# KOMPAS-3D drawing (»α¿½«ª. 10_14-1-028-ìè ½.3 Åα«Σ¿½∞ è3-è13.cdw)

Referenced files in C:\Program Files\ASCON\KOMPAS-3D V10\Sys\: SPDS.lcs, Graphic.lcs
Referenced files: профиль К3-К13.cdw
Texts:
  Текст на чертеже
  Размерные надписи
  Шероховатость
  Линия-выноска #1
  Линия-выноска #2
  Линия-выноска #3
  Отклонения формы и база
  Заголовок таблицы
  Ячейка таблицы
  Стрелка вида
  Обозначение изменения
  Фигурная скобка
  Номер узла
  Марка координационной оси
  VRCB
  Выносная надпись
  Обозначение узла
  Марка/позиционное обозначение с линией-выноской
  Марка/позиционное обозначение на линии
  Марка/позиционное обозначение без линии-выноски
  Normal
  TXT
  Courier New Cyr
  txt
  Body Text
  heading 1
  Знак Знак Знак Знак Знак Знак
  Verdana
  Лит-Масса-Масштаб
  Материал-Предприятие
  MS Sans Serif
  Simplex
  Txt
  Title Specification
  Body Specification ( left align )
  Body Specificaton ( centered )
  Без имени
  Additional DXF text style 0
  Обычный
  Термин
  Список определений
  Адрес
  Цитаты
  Форматированный
  Courier New
  Z-конец формы
  Z-начало формы
  ТекстШаг1
  Денис
  heading 2
  AGOpus
  footer
  Title
  ООббыыччнныыйй
  Definition Term
  Definition List
  Address
  Blockquote
  Preformatted
  z-Bottom of Form
  z-Top of Form
  header
  heading 8
  heading 3
  heading 6
  heading 7
  russ
  ТТееррммиинн
  ССппииссоокк ооппррееддееллеенниийй
  ААддрреесс
  ЦЦииттааттыы
  ФФооррммааттиирроовваанннныыйй
  Z-ккооннеецц ффооррммыы
  Z-ннааччааллоо ффооррммыы
  Абзац Знак
  heading 4
  heading 5
  heading 9
  GOST 2.304 type A
  rustxt
  цепи
  ссылки
  Маркировка
  Подпись в квадратике
  табл
  ЗОНА_привяз
  маркировка
  ГОСТ_МНЕ
  ESK - Обозначение
  текст переноса
  Тексты. 3,2
  Body Text 3
  клеммы, контакты
  тексты табл
  ISOCP
  HeliosLight
  Pa3
  Pa1
  Шрифт 2.5
  Заголовки
  RUSTXT
  NormalParagraphStyle
  Три с половиной
  style2
  Table Contents
  Table Heading
  CNBNDG+TimesNewRoman
  Subtitle
  ISOCPEUR
  Текст 3,5
  Tahoma
  форма профиля
  узел А
  Номер колодца, точки,
  угла поворота
  Расстояние, м
  Уклон,
  Длина, м
  Основание
  Натурная отметка
  земли
  Отметка низа или лотка
  трубы
  Обозначение трубы и
  тип изоляции
  Проектная отметка
  насос
  МП1
  уг1
  Песчаная засыпка д=300мм над
  и подсыпка 100мм под трубой
  Труба чугунная ЧНР  300
  ГОСТ 9583-75
  уг3
  Естественное
  Труба напорная ПЭ80 SDR13,6
  Symbol type A
  Мсб
  маслосборник
  Накопительный
  резервуар
  Футляр L=12,5м
  уг2
  уг.поворота 157
  Футляр L=14,5м
  а/дорога
  Стяжка В 7,5
  W6 t=50мм
  Ось
  приямка
  Узел А
  (см. комплект 10/14-1-113-КС)
  Сетка латунная
  Решетка М-5
  Бетон
  Примечания:
  1. Отметки и размеры со знаком "*" уточнить по месту.
  2. Смотреть совместно с комплектами 10/14-1-113-КС и 10/14-1-259-НК.
  см. 10/14-1-259-НК
  Промытый и просеянный
  гравий или непористый
  щебень от 30 до 50 мм
  STROT_RGB_128_32_0_SC_1_THICK_0.18
  CONTI_RGB_0_0_0_THICK_0.18
  POLYLINE_STYLE_0.30_RGB_0_0_0
  POLYLINE_STYLE_0.18_RGB_0_0_0
  ACAD_ISO02W100_RGB_0_0_255_SC_1_THICK_0.3
  POLYLINE_STYLE_0.60_RGB_0_0_255
  ACAD_ISO02W100_RGB_0_0_0_SC_1_THICK_0.15
  POLYLINE_STYLE_0.18_RGB_255_0_0
  K5LT_AXLED_RGB_255_128_0_SC_1_THICK_0.09
  POLYLINE_STYLE_0.30_RGB_255_0_255
  POLYLINE_STYLE_0.20_RGB_0_0_0
  POLYLINE_STYLE_0.25_RGB_128_64_0
  POLYLINE_STYLE_0.18_RGB_128_64_0
  POLYLINE_STYLE_0.18_RGB_0_80_80
  K5LT_AXLED_RGB_255_128_0_SC_1_THICK_0.18
  K5LT_THIN_RGB_0_0_0_THICK_0.09
  K5LT_THIN_RGB_0_0_0_THICK_0.13
  СONTINUOUS_RGB_255_0_0_THICK_0.6
  ACAD_ISO04W100_RGB_255_0_0_SC_1_THICK_0.13
  Ультрас О 0,3
  K5LT_BASIC_RGB_0_0_255_THICK_0.2
  CONTINUOUS_RGB_0_0_0_THICK_0.2
  Стили документа
  ГОСТ 8509-93
  Н. контр
  Ромин
  Орлова
  Разраб.
  Галактионов
  Реконструкция ПС 110 кВ Опорная
  (замена трансформаторов 16МВА на 40МВА)
  Профиль сетей К3, К3Н, К13
  Аварийные маслостоки
Dimensions and other numbers on the sheet: 10/14-1-028-НК; 7; 3,2_; 2,5; 3.5; 2.5; 1,8; 2,5 (контакты, клеммы); 2.5 курсив; 2,5_3; 3,2 (надписи); 3,5_01; 2,5_01; 3,5_tabl; 5_заголовок; 2,3_; 3,2_зона не привяз; 2,5 грязносинь; 5,0_белый_подчёркнутый; 3,2; 3.2 фиол; 3,5; 5; 3,2 элементы; 3,2 линия; 3,2 таблица; 3.2 маркировка; 2.5_Э5_надписи; 2.5_Э5_ссылки; 2.5_кабель; 3.2; 2.5 надписи; 3,2 (Зоны); 3 и 5; 3.2 (текст); 1,40; 100,00; 99,00; 98,00; 97,00; 96,00; 95,00; 1; 3,3; 22,5; 10; 14,8; 25,8; 15,8; 98,820; 101,450; 100,000; 100,180; 98,912; 98,900; 98,750; 99,300; 97,300; 100,100; 100,350; 100,250; 100,050; 100,230; 99,900; 98,910; 102,160; 1,0; 98,700; 600; 100; 300; 200; 500*; 11.12; 10/14-1-НВК-; 3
